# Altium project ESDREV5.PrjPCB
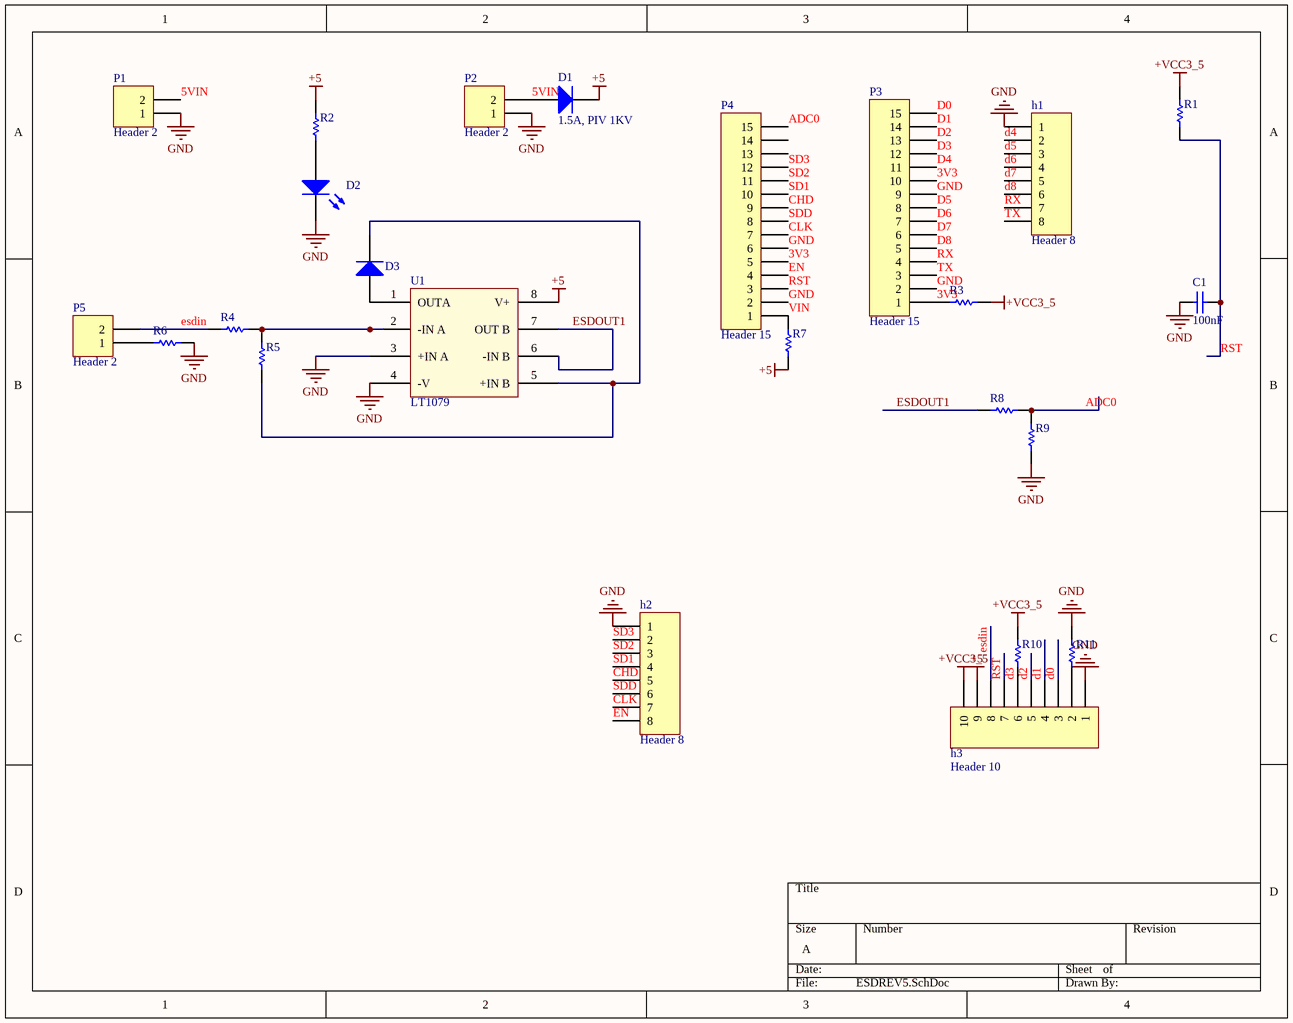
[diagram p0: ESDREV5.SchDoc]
1 sheet, 24 parts. Net scope: global (net labels, ports and power ports of the same name join across sheets).
Board file: ESDREV5.PcbDoc

## Sheet ESDREV5.SchDoc: ANSARI
size A

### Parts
C1  100nF  [0805]
D1  1.5A, PIV 1KV  [DO-214AA]
D2  LED3  [0537, LED, 1206]  (value not drawn)
D3  Diode 1N4448  [DO-35]  (value not drawn)
h1  Header 8  [HDR1X8]
h2  Header 8  [HDR1X8]
h3  Header 10  [HDR1X10]
P1  Header 2  [DCJACK]
P2  Header 2  [DCJACK]
P3  Header 15  [HDR1X15]
P4  Header 15  [HDR1X15]
P5  Header 2  [HDR1X2]
R1  (no value)  [0805]
R2  R  [0805]  (value not drawn)
R3  (no value)  [0805]
R4  R  [0805]  (value not drawn)
R5  R  [0805]  (value not drawn)
R6  (no value)  [0805]
R7  (no value)  [0805]
R8  (no value)  [0805]
R9  (no value)  [0805]
R10  (no value)  [0805]
R11  (no value)  [0805]
U1  LT1079  [DIP-8]

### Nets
+5: D1.K h3.9 R2.2 R7.2 U1.8(V+)
+VCC3_5: h3.10 R1.2 R3.1 R10.2
GND: C1.1 D2.K h1.1 h2.1 h3.1 P1.2(1) P2.2(1) P3.2 P3.9 P4.2 P4.6 R6.1 R9.1 R11.2 U1.3(+IN_A) U1.4(-V)
3V3: P3.1 P3.10 P4.5 R3.2
5VIN: D1.A P1.1(2) P2.1(2)
ADC0: P4.15 R8.1 R9.2
CHD: h2.5 P4.9
CLK: h2.7 P4.7
D0: h3.3 P3.15
D1: h3.4 P3.14
D2: h3.5 P3.13
D3: h3.6 P3.12 R10.1
D4: h1.2 P3.11
D5: h1.3 P3.8
D6: h1.4 P3.7
D7: h1.5 P3.6
D8: h1.6 P3.5
EN: h2.8 P4.4
esdin: h3.8 P5.2 R4.1
ESDOUT1: R8.2 U1.6(-IN_B) U1.7(OUT_B)
RST: C1.2 h3.7 P4.3 R1.1
RX: h1.7 P3.4
SD1: h2.4 P4.10
SD2: h2.3 P4.11
SD3: h2.2 P4.12
SDD: h2.6 P4.8
TX: h1.8 P3.3
VIN: P4.1 R7.1
NetD2_A: D2.A R2.1
NetD3_1: D3.1(A) U1.1(OUTA)
NetD3_2: D3.2(K) R5.1 U1.5(+IN_B)
Neth3_2: h3.2 R11.1
NetP5_1: P5.1 R6.2
NetR4_2: R4.2 R5.2 U1.2(-IN_A)

Not connected (* = marked no-connect by the designer): P4 13 14

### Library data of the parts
C1 = CAPACITOR NONPOLAR SMT: Capacitor ceramic, SMD 0603, 10 UF, +/-10%, 16 V dc; SMLPARTNO: BCS129-104; Mfr Name: KEMET; Units of Voltage: V dc; Value(Farad): 100U; Voltage Rating: 16; Units of Capacitance: nF; Dielectric: X7R; Capacitance: 100
D1 = DIODE: Diode high voltage, SMD DO-214AA, If 1.5 A, PIV 1 kV; SMLPARTNO: BDS334-001; Mfr Name: VISHAY; Secure Use Status: Authorization Required; Peak Inverse Voltage: 1; Average Forward Current: 1.5
D2 = LED3: Typical BLUE SiC LED
D3 = Diode 1N4448: High Conductance Fast Diode
h1 h2 = Header 8: Header, 8-Pin
h3 = Header 10: Header, 10-Pin
P1 P2 P5 = Header 2: Header, 2-Pin
P3 P4 = Header 15: Header, 15-Pin
R1 R6 = BRS133-473: Resistor SMD 0603, 4.7 k Ohm, +/-5%, 1/10W; SMLPARTNO: BRS133-472; Mfr Name: VISHAY; Sub Category: Thick Film; Resistance: 4.7k; Tempco1: 0.0002; Unit Of Resistance: k Ohm; Value(ohm): 4.7
R2 = BRS133-473: Resistor SMD 0603, 4.7 k Ohm, +/-5%, 1/10W; SMLPARTNO: BRS133-472; Mfr Name: VISHAY; Sub Category: Thick Film; Resistance: 47; Tempco1: 0.0002; Unit Of Resistance: k Ohm; Value(ohm): 4.7k
R3 R8 = BRS133-473: Resistor SMD 0805, 1.5 k Ohm, +/-1%, 1/8W; SMLPARTNO: BRS121-152; Mfr Name: VISHAY; Sub Category: Thick Film; Resistance: 1.5; Tempco1: 0.0002; Value(ohm): 1.5 K; Tolerance: +/-5%; Power Rating: 1/10W
R4 = BRS133-473: Resistor SMD 0805, 220 k Ohm, +/-1%, 1/8W; SMLPARTNO: BRS121-224; Mfr Name: VISHAY; Sub Category: Thick Film; Resistance: 220; Tempco1: 0.0002; Unit Of Resistance: k Ohm; Tolerance: +/-5%; Power Rating: 1/10W
R5 = BRS133-473: Resistor SMD 0805, 220 k Ohm, +/-1%, 1/8W; SMLPARTNO: BRS121-224; Mfr Name: VISHAY; Sub Category: Thick Film; Resistance: 220; Tempco1: 0.0002; Unit Of Resistance: k Ohm; Value(ohm): 200k; Tolerance: +/-5%; Power Rating: 1/10W
R7 = BRS133-473: Resistor SMD 0603, 0 Ohm, +/-5%, 1/10W; SMLPARTNO: BRS133-0; Mfr Name: VISHAY; Sub Category: Thick Film; Resistance: 4.7; Tempco1: 0.0002; Value(ohm): 0
R9 = BRS133-473: Resistor SMD 1206, 10 k Ohm, +/-5%, 1/4W; SMLPARTNO: BRS005-103; Mfr Name: VISHAY; Sub Category: Thick Film; Resistance: 10; Tempco1: 0.0002; Value(ohm): 10 K; Power Rating: 1/10W
R10 R11 = BRS133-473: Resistor SMD 0603, 470 Ohm, +/-5%, 1/10W; SMLPARTNO: BRS133-471; Mfr Name: VISHAY; Sub Category: Thick Film; Resistance: 4.7; Tempco1: 0.0002; Value(ohm): 470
